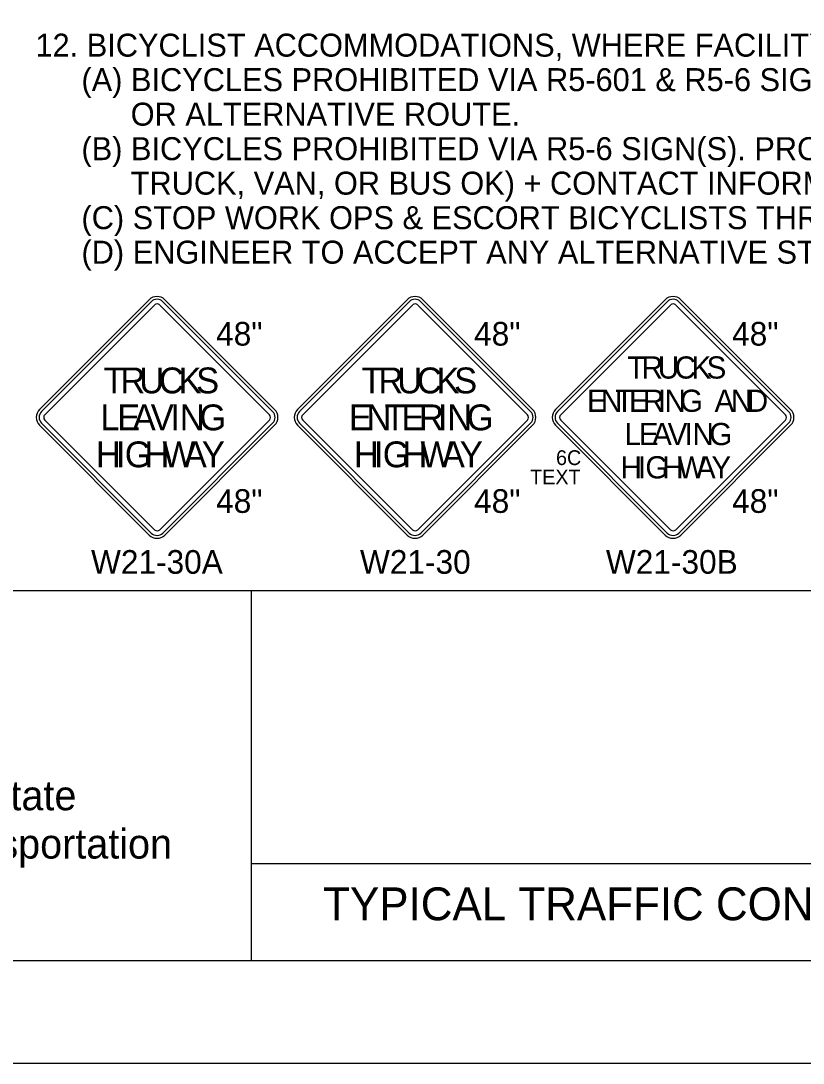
# Model space of a CAD drawing. Extents: x 99958 to 100176, y 99935 to 100011.
# Drawn here: x 100031.504 to 100033.887, y 99999.687 to 100002.86 of the extents above; entities that cross this region are included whole.
import ezdxf

# ---------------------------------------------------------------- set-up
doc = ezdxf.new("R2010")
doc.units = 0
for name, color, linetype in [('SH_GI_GeneralNotesBodyText', 7, 'Continuous'), ('SH_GI_PlotLimits', 7, 'Continuous'), ('SH_GI_SheetBorder', 7, 'Continuous'), ('SH_GI_SheetTextInCells', 7, 'Continuous'), ('SH_GI_TitleBlockText', 7, 'Continuous'), ('TR_SN_ConstructionSigns', 7, 'Continuous')]:
    doc.layers.add(name, color=color, linetype=linetype)

msp = doc.modelspace()

# ---------------------------------------------------------------- linework, layer by layer
at = {"layer": 'SH_GI_PlotLimits'}
msp.add_lwpolyline([(100019.0625, 99999.6875), (100036.0625, 99999.6875), (100036.0625, 100010.6875), (100019.0625, 100010.6875)], close=True, dxfattribs=at)
at = {"layer": 'SH_GI_SheetBorder'}
for p, q in [((100020, 100001.1259), (100035.75, 100001.1259)), ((100032.2055, 100001.1259), (100032.2055, 100000)), ((100032.2055, 100000.2955), (100035.2079, 100000.2955)), ((100020, 100000), (100035.75, 100000))]:
    msp.add_line(p, q, dxfattribs=at)
at = {"layer": 'TR_SN_ConstructionSigns'}
for p, q in [((100031.8955, 100002.0107), (100031.5613, 100001.6766)), ((100031.9014, 100002.0048), (100031.5673, 100001.6707)), ((100032.2713, 100001.6707), (100031.9372, 100002.0048)), ((100032.2773, 100001.6766), (100031.9432, 100002.0107)), ((100032.6812, 100002.0107), (100032.3471, 100001.6766)), ((100032.6871, 100002.0048), (100032.353, 100001.6707)), ((100033.057, 100001.6707), (100032.7229, 100002.0048)), ((100033.063, 100001.6766), (100032.7289, 100002.0107)), ((100033.4669, 100002.0107), (100033.1328, 100001.6766)), ((100033.4729, 100002.0048), (100033.1387, 100001.6707)), ((100033.8428, 100001.6707), (100033.5087, 100002.0048)), ((100033.8487, 100001.6766), (100033.5146, 100002.0107)), ((100031.5773, 100001.6607), (100031.9114, 100001.9948)), ((100031.9273, 100001.9948), (100032.2614, 100001.6607)), ((100032.363, 100001.6607), (100032.6971, 100001.9948)), ((100032.713, 100001.9948), (100033.0471, 100001.6607)), ((100033.1487, 100001.6607), (100033.4828, 100001.9948)), ((100033.4987, 100001.9948), (100033.8328, 100001.6607)), ((100031.5613, 100001.6289), (100031.8955, 100001.2948)), ((100031.5673, 100001.6349), (100031.9014, 100001.3008)), ((100031.9114, 100001.3107), (100031.5773, 100001.6448)), ((100032.2614, 100001.6448), (100031.9273, 100001.3107)), ((100031.9372, 100001.3008), (100032.2713, 100001.6349)), ((100031.9432, 100001.2948), (100032.2773, 100001.6289)), ((100032.3471, 100001.6289), (100032.6812, 100001.2948)), ((100032.353, 100001.6349), (100032.6871, 100001.3008)), ((100032.6971, 100001.3107), (100032.363, 100001.6448)), ((100033.0471, 100001.6448), (100032.713, 100001.3107)), ((100032.7229, 100001.3008), (100033.057, 100001.6349)), ((100032.7289, 100001.2948), (100033.063, 100001.6289)), ((100033.1328, 100001.6289), (100033.4669, 100001.2948)), ((100033.1387, 100001.6349), (100033.4729, 100001.3008)), ((100033.4828, 100001.3107), (100033.1487, 100001.6448)), ((100033.8328, 100001.6448), (100033.4987, 100001.3107)), ((100033.5087, 100001.3008), (100033.8428, 100001.6349)), ((100033.5146, 100001.2948), (100033.8487, 100001.6289))]:
    msp.add_line(p, q, dxfattribs=at)
for centre, radius, start, end in [((100031.9193, 100001.9869), 0.0338, 45, 135), ((100031.9193, 100001.9869), 0.0253, 45, 135), ((100031.9193, 100001.9869), 0.0113, 45, 135), ((100032.705, 100001.9869), 0.0338, 45, 135), ((100032.705, 100001.9869), 0.0253, 45, 135), ((100032.705, 100001.9869), 0.0113, 45, 135), ((100033.4908, 100001.9869), 0.0338, 45, 135), ((100033.4908, 100001.9869), 0.0253, 45, 135), ((100033.4908, 100001.9869), 0.0113, 45, 135), ((100031.5852, 100001.6528), 0.0338, 135, 225), ((100031.5852, 100001.6528), 0.0253, 135, 225), ((100031.5852, 100001.6528), 0.0113, 135, 225), ((100032.2534, 100001.6528), 0.0113, 315, 45), ((100032.2534, 100001.6528), 0.0253, 315, 45), ((100032.2534, 100001.6528), 0.0338, 315, 45), ((100032.3709, 100001.6528), 0.0338, 135, 225), ((100032.3709, 100001.6528), 0.0253, 135, 225), ((100032.3709, 100001.6528), 0.0113, 135, 225), ((100033.0391, 100001.6528), 0.0113, 315, 45), ((100033.0391, 100001.6528), 0.0253, 315, 45), ((100033.0391, 100001.6528), 0.0338, 315, 45), ((100033.1566, 100001.6528), 0.0338, 135, 225), ((100033.1566, 100001.6528), 0.0253, 135, 225), ((100033.1566, 100001.6528), 0.0113, 135, 225), ((100033.8249, 100001.6528), 0.0113, 315, 45), ((100033.8249, 100001.6528), 0.0253, 315, 45), ((100033.8249, 100001.6528), 0.0338, 315, 45), ((100031.9193, 100001.3187), 0.0253, 225, 315), ((100031.9193, 100001.3187), 0.0113, 225, 315), ((100032.705, 100001.3187), 0.0253, 225, 315), ((100032.705, 100001.3187), 0.0113, 225, 315), ((100033.4908, 100001.3187), 0.0253, 225, 315), ((100033.4908, 100001.3187), 0.0113, 225, 315), ((100031.9193, 100001.3187), 0.0338, 225, 315), ((100032.705, 100001.3187), 0.0338, 225, 315), ((100033.4908, 100001.3187), 0.0338, 225, 315)]:
    msp.add_arc(centre, radius, start, end, dxfattribs=at)

# ---------------------------------------------------------------- texts
at = {"layer": 'SH_GI_GeneralNotesBodyText'}
for s, p in [('12. BICYCLIST ACCOMMODATIONS, WHERE FACILITY OPEN TO BICYCLES:', (100031.549, 100002.7506)), ('(A) BICYCLES PROHIBITED VIA R5-601 & R5-6 SIGNS. PROVIDE SIGNED DETOUR ', (100031.689, 100002.6456)), ('OR ALTERNATIVE ROUTE.', (100031.839, 100002.5406)), ('(B) BICYCLES PROHIBITED VIA R5-6 SIGN(S). PROVIDE FREE SHUTTLE (WORK ', (100031.689, 100002.4356)), ('TRUCK, VAN, OR BUS OK) + CONTACT INFORMATION/PHONE BOX/LABORER. ', (100031.839, 100002.3306)), ('(C) STOP WORK OPS & ESCORT BICYCLISTS THROUGH CLOSURE.', (100031.689, 100002.2256)), ('(D) ENGINEER TO ACCEPT ANY ALTERNATIVE STRATEGIES.', (100031.689, 100002.1206))]:
    msp.add_text(s, height=0.07, rotation=360, dxfattribs=at).set_placement(p)
at = {"layer": 'SH_GI_SheetTextInCells'}
for s, p in [('Washington State', (100030.7229, 100000.4571)), ('Department of Transportation', (100030.3916, 100000.3101))]:
    msp.add_text(s, height=0.090072, dxfattribs=at).set_placement(p)
at = {"layer": 'SH_GI_TitleBlockText'}
msp.add_text('TYPICAL TRAFFIC CONTROL PLANS', height=0.1, dxfattribs=at).set_placement((100032.4251, 100000.1224))
at = {"layer": 'TR_SN_ConstructionSigns'}
for s, p in [('48"', (100032.0991, 100001.8713)), ('48"', (100032.8848, 100001.8713)), ('48"', (100033.6706, 100001.8713)), ('48"', (100032.0991, 100001.3622)), ('48"', (100032.8848, 100001.3622)), ('48"', (100033.6706, 100001.3622)), ('W21-30A', (100031.7182, 100001.1769)), ('W21-30', (100032.5373, 100001.1769)), ('W21-30B', (100033.2863, 100001.1769))]:
    msp.add_text(s, height=0.072, rotation=360, dxfattribs=at).set_placement(p)
for s, height, p in [('T', 0.0675, (100033.351, 100001.7709)), ('R', 0.0675, (100033.3949, 100001.7709)), ('U', 0.0675, (100033.4442, 100001.7709)), ('C', 0.0675, (100033.4955, 100001.7709)), ('K', 0.0675, (100033.5468, 100001.7709)), ('S', 0.0675, (100033.5927, 100001.7709)), ('T', 0.0787, (100031.7563, 100001.7259)), ('R', 0.0787, (100031.8075, 100001.7259)), ('U', 0.0787, (100031.865, 100001.7259)), ('C', 0.0787, (100031.9248, 100001.7259)), ('K', 0.0787, (100031.9847, 100001.7259)), ('S', 0.0787, (100032.0382, 100001.7259)), ('T', 0.0787, (100032.542, 100001.7259)), ('R', 0.0787, (100032.5932, 100001.7259)), ('U', 0.0787, (100032.6507, 100001.7259)), ('C', 0.0787, (100032.7106, 100001.7259)), ('K', 0.0787, (100032.7704, 100001.7259)), ('S', 0.0787, (100032.824, 100001.7259)), ('E', 0.0675, (100033.2286, 100001.6696)), ('N', 0.0675, (100033.271, 100001.6696)), ('T', 0.0675, (100033.3154, 100001.6696)), ('E', 0.0675, (100033.3565, 100001.6696)), ('R', 0.0675, (100033.3989, 100001.6696)), ('I', 0.0675, (100033.4448, 100001.6696)), ('N', 0.0675, (100033.4646, 100001.6696)), ('G', 0.0675, (100033.5118, 100001.6696)), ('A', 0.0675, (100033.6171, 100001.6696)), ('N', 0.0675, (100033.667, 100001.6696)), ('D', 0.0675, (100033.7152, 100001.6696)), ('L', 0.0787, (100031.7465, 100001.6134)), ('E', 0.0787, (100031.7977, 100001.6134)), ('A', 0.0787, (100031.8449, 100001.6134)), ('V', 0.0787, (100031.9, 100001.6134)), ('I', 0.0787, (100031.9599, 100001.6134)), ('N', 0.0787, (100031.9882, 100001.6134)), ('G', 0.0787, (100032.0481, 100001.6134)), ('E', 0.0787, (100032.5034, 100001.6134)), ('N', 0.0787, (100032.557, 100001.6134)), ('T', 0.0787, (100032.6121, 100001.6134)), ('E', 0.0787, (100032.6633, 100001.6134)), ('R', 0.0787, (100032.7169, 100001.6134)), ('I', 0.0787, (100032.7743, 100001.6134)), ('N', 0.0787, (100032.8027, 100001.6134)), ('G', 0.0787, (100032.8625, 100001.6134)), ('L', 0.0675, (100033.3426, 100001.5684)), ('E', 0.0675, (100033.3865, 100001.5684)), ('A', 0.0675, (100033.427, 100001.5684)), ('V', 0.0675, (100033.4742, 100001.5684)), ('I', 0.0675, (100033.5255, 100001.5684)), ('N', 0.0675, (100033.5498, 100001.5684)), ('G', 0.0675, (100033.6011, 100001.5684)), ('H', 0.0787, (100031.7327, 100001.5009)), ('I', 0.0787, (100031.7941, 100001.5009)), ('G', 0.0787, (100031.8209, 100001.5009)), ('H', 0.0787, (100031.8807, 100001.5009)), ('W', 0.0787, (100031.9359, 100001.5009)), ('A', 0.0787, (100032.0004, 100001.5009)), ('Y', 0.0787, (100032.0556, 100001.5009)), ('H', 0.0787, (100032.5184, 100001.5009)), ('I', 0.0787, (100032.5798, 100001.5009)), ('G', 0.0787, (100032.6066, 100001.5009)), ('H', 0.0787, (100032.6665, 100001.5009)), ('W', 0.0787, (100032.7216, 100001.5009)), ('A', 0.0787, (100032.7862, 100001.5009)), ('Y', 0.0787, (100032.8413, 100001.5009)), ('6C', 0.045, (100033.1343, 100001.5077)), ('H', 0.0675, (100033.3308, 100001.4671)), ('I', 0.0675, (100033.3834, 100001.4671)), ('G', 0.0675, (100033.4064, 100001.4671)), ('H', 0.0675, (100033.4577, 100001.4671)), ('W', 0.0675, (100033.5049, 100001.4671)), ('A', 0.0675, (100033.5603, 100001.4671)), ('Y', 0.0675, (100033.6075, 100001.4671)), ('TEXT', 0.045, (100033.0554, 100001.4491))]:
    msp.add_text(s, height=height, dxfattribs=at).set_placement(p)

doc.saveas('drawing.dxf')
